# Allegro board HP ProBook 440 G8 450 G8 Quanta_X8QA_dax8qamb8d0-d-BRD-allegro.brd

Outline 218.84 x 120.25 mm; copper layers: TOP, SGND, IN1, SVCC, IN2, IN3, SGND1, BOTTOM. Coordinates in mm from the lower left corner of the outline.

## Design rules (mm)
constraint set DEFAULT: min track width 0.109
net group DFP-S3.1W10-T123B: nets N38936236 N38936237
net group W4.5-T13B: nets VCCSENSE VSSSENSE
net group W8(8: nets GPU_VCC_SENSE GPU_VSS_SENSE
net group W12-T13B: nets PCIE_RCOMPN PCIE_RCOMPP
net group W15-T123B: nets +VCCSTG CFG_RCOMP
net group DFP-S3.5(3.1: nets USB30_RX1+ USB30_RX1- USB30_RX2+ USB30_RX2- USB30_RX4+ USB30_RX4- USB30_TX1+ USB30_TX1+_C USB30_TX1- USB30_TX1-_C USB30_TX2+ USB30_TX2+_C USB30_TX2- USB30_TX2-_C USB30_TX4+ USB30_TX4-
net group DFP-S4.5(3.5: nets C_TX0_HDMI+ C_TX0_HDMI- C_TX1_HDMI+ C_TX1_HDMI- C_TX2_HDMI+ C_TX2_HDMI- C_TXC_HDMI+ C_TXC_HDMI- CCG6_SBU1_A CCG6_SBU1_A_M CCG6_SBU1_R_A CCG6_SBU2_A CCG6_SBU2_A_M CCG6_SBU2_R_A CK_XDP_N CK_XDP_P CLK_GFX_N CLK_GFX_P CLK_PCIE_CRN CLK_PCIE_CRP CLK_PCIE_LANN CLK_PCIE_LANN_R CLK_PCIE_LANP CLK_PCIE_LANP_R CLK_PCIE_SSDN CLK_PCIE_SSDP CLK_PCIE_WLANN CLK_PCIE_WLANP CLK_PCIE_WWANN CLK_PCIE_WWANP EDIDCLK_R EDIDDATA_R IN_CLK IN_CLK# IN_D0 IN_D0# IN_D1 IN_D1# IN_D2 IN_D2# INT_EDP_AUXN INT_EDP_AUXP INT_EDP_TXN0 INT_EDP_TXN1 INT_EDP_TXP0 INT_EDP_TXP1 M_A_CLKN0 M_A_CLKN1 M_A_CLKP0 M_A_CLKP1 M_B_CLKN0 M_B_CLKN1 M_B_CLKP0 M_B_CLKP1 PCIE_RXN5_LAN PCIE_RXN6_SD PCIE_RXN6_SD_C PCIE_RXN7_WLAN PCIE_RXN8_WWAN PCIE_RXN9_SSD PCIE_RXN10_SSD PCIE_RXN11_SSD PCIE_RXN12_SSD PCIE_RXP5_LAN PCIE_RXP6_SD PCIE_RXP6_SD_C PCIE_RXP7_WLAN PCIE_RXP8_WWAN PCIE_RXP9_SSD PCIE_RXP10_SSD PCIE_RXP11_SSD PCIE_RXP12_SSD PCIE_TXN5_LAN_C PCIE_TXN6_SD PCIE_TXN6_SD_C PCIE_TXN7_WLAN PCIE_TXN7_WLAN_C PCIE_TXN8_WWAN PCIE_TXN8_WWAN_C PCIE_TXN9_SSD PCIE_TXN9_SSD_C PCIE_TXN10_SSD PCIE_TXN10_SSD_C1 PCIE_TXN11_SSD PCIE_TXN11_SSD_C PCIE_TXN12_SSD PCIE_TXN12_SSD_C PCIE_TXP5_LAN_C PCIE_TXP6_SD PCIE_TXP6_SD_C PCIE_TXP7_WLAN PCIE_TXP7_WLAN_C PCIE_TXP8_WWAN PCIE_TXP8_WWAN_C PCIE_TXP9_SSD PCIE_TXP9_SSD_C PCIE_TXP10_SSD PCIE_TXP10_SSD_C1 PCIE_TXP11_SSD PCIE_TXP11_SSD_C PCIE_TXP12_SSD PCIE_TXP12_SSD_C PEX_TSTCLK PEX_TSTCLK# TBTA_SSRX1_N TBTA_SSRX1_N_C TBTA_SSRX1_P TBTA_SSRX1_P_C TBTA_SSRX2_N TBTA_SSRX2_N_C TBTA_SSRX2_P TBTA_SSRX2_P_C TBTA_SSTX1_N TBTA_SSTX1_N_C TBTA_SSTX1_P TBTA_SSTX1_P_C TBTA_SSTX2_N TBTA_SSTX2_N_C TBTA_SSTX2_P TBTA_SSTX2_P_C TCP0_AUX_DN TCP0_AUX_DN_R TCP0_AUX_DP TCP0_AUX_DP_R TCP0_DIRECT_TX0_R_DN TCP0_DIRECT_TX0_R_DP TCP0_DIRECT_TX1_R_DN TCP0_DIRECT_TX1_R_DP TCP0_DIRECT_TXRX0_R_DN TCP0_DIRECT_TXRX0_R_DP TCP0_DIRECT_TXRX1_R_DN TCP0_DIRECT_TXRX1_R_DP TCP0_TX_N0 TCP0_TX_N0_C TCP0_TX_N1 TCP0_TX_N1_C TCP0_TX_P0 TCP0_TX_P0_C TCP0_TX_P1 TCP0_TX_P1_C TCP0_TXRX_N0 TCP0_TXRX_N0_C TCP0_TXRX_N1 TCP0_TXRX_N1_C TCP0_TXRX_P0 TCP0_TXRX_P0_C TCP0_TXRX_P1 TCP0_TXRX_P1_C TCP1_AUX_DN_C TCP1_AUX_DP_C TX0_HDMI+ TX0_HDMI- TX1_HDMI+ TX1_HDMI- TX2_HDMI+ TX2_HDMI- TXC_HDMI+ TXC_HDMI- TXLOUT0+ TXLOUT0- TXLOUT1+ TXLOUT1- TYPEC3_RX1N_C TYPEC3_RX1P_C TYPEC3_RX2N_C TYPEC3_RX2P_C TYPEC3_TX1N_C TYPEC3_TX1P_C TYPEC3_TX2N_C TYPEC3_TX2P_C USB_CYPRESS_BOT_DN USB_CYPRESS_BOT_DP USB_CYPRESS_TOP_DN USB_CYPRESS_TOP_DP USBC_ALT_AUX_NBIAS USBC_ALT_AUX_PBIAS USBP1+ USBP1+_C USBP1+_CHA USBP1- USBP1-_C USBP1-_CHA USBP2+ USBP2+_C USBP2- USBP2-_C USBP4+ USBP4+_C USBP4- USBP4-_C USBP5+ USBP5- USBP6+ USBP6- USBP7+ USBP7+_C USBP7- USBP7-_C USBP8+ USBP8+_C USBP8- USBP8-_C USBP9+ USBP9- USBP10+ USBP10+_C USBP10- USBP10-_C VMA_CLK0 VMA_CLK0# VMA_CLK1 VMA_CLK1# VMA_WCK01 VMA_WCK01# VMA_WCK23 VMA_WCK23# VMA_WCK45 VMA_WCK45# VMA_WCK67 VMA_WCK67# WR_CLK_DN WR_CLK_DP WR_LANE0_DN WR_LANE0_DP WR_LANE1_DN WR_LANE1_DP WT_CLK_DN WT_CLK_DP WT_LANE0_DN WT_LANE0_DP WT_LANE1_DN WT_LANE1_DP
net group DFP-S4.5(6: nets PEG_RXN1 PEG_RXN1_C PEG_RXN2 PEG_RXN2_C PEG_RXN3 PEG_RXN3_C PEG_RXN4 PEG_RXN4_C PEG_RXP1 PEG_RXP1_C PEG_RXP2 PEG_RXP2_C PEG_RXP3 PEG_RXP3_C PEG_RXP4 PEG_RXP4_C PEG_TXN1 PEG_TXN1_C PEG_TXN2 PEG_TXN2_C PEG_TXN3 PEG_TXN3_C PEG_TXN4 PEG_TXN4_C PEG_TXP1 PEG_TXP1_C PEG_TXP2 PEG_TXP2_C PEG_TXP3 PEG_TXP3_C PEG_TXP4 PEG_TXP4_C
net group DFP-S7(4.5: nets 27M_XTAL_IN 27M_XTAL_OUT M_A_DQSN0 M_A_DQSN1 M_A_DQSN2 M_A_DQSN3 M_A_DQSN4 M_A_DQSN5 M_A_DQSN6 M_A_DQSN7 M_A_DQSP0 M_A_DQSP1 M_A_DQSP2 M_A_DQSP3 M_A_DQSP4 M_A_DQSP5 M_A_DQSP6 M_A_DQSP7 M_B_DQSN0 M_B_DQSN1 M_B_DQSN2 M_B_DQSN3 M_B_DQSN4 M_B_DQSN5 M_B_DQSN6 M_B_DQSN7 M_B_DQSP0 M_B_DQSP1 M_B_DQSP2 M_B_DQSP3 M_B_DQSP4 M_B_DQSP5 M_B_DQSP6 M_B_DQSP7
net group M_0_DQ_0: nets M_0_DQ_0<0> M_0_DQ_0<1> M_0_DQ_0<2> M_0_DQ_0<3> M_0_DQ_0<4> M_0_DQ_0<5> M_0_DQ_0<6> M_0_DQ_0<7>
net group M_0_DQ_1: nets M_0_DQ_1<0> M_0_DQ_1<1> M_0_DQ_1<2> M_0_DQ_1<3> M_0_DQ_1<4> M_0_DQ_1<5> M_0_DQ_1<6> M_0_DQ_1<7>
net group M_0_DQ_2: nets M_0_DQ_2<0> M_0_DQ_2<1> M_0_DQ_2<2> M_0_DQ_2<3> M_0_DQ_2<4> M_0_DQ_2<5> M_0_DQ_2<6> M_0_DQ_2<7>
net group M_0_DQ_3: nets M_0_DQ_3<0> M_0_DQ_3<1> M_0_DQ_3<2> M_0_DQ_3<3> M_0_DQ_3<4> M_0_DQ_3<5> M_0_DQ_3<6> M_0_DQ_3<7>
net group M_0_DQ_4: nets M_0_DQ_4<0> M_0_DQ_4<1> M_0_DQ_4<2> M_0_DQ_4<3> M_0_DQ_4<4> M_0_DQ_4<5> M_0_DQ_4<6> M_0_DQ_4<7>
net group M_0_DQ_5: nets M_0_DQ_5<0> M_0_DQ_5<1> M_0_DQ_5<2> M_0_DQ_5<3> M_0_DQ_5<4> M_0_DQ_5<5> M_0_DQ_5<6> M_0_DQ_5<7>
net group M_0_DQ_6: nets M_0_DQ_6<0> M_0_DQ_6<1> M_0_DQ_6<2> M_0_DQ_6<3> M_0_DQ_6<4> M_0_DQ_6<5> M_0_DQ_6<6> M_0_DQ_6<7>
net group M_0_DQ_7: nets M_0_DQ_7<0> M_0_DQ_7<1> M_0_DQ_7<2> M_0_DQ_7<3> M_0_DQ_7<4> M_0_DQ_7<5> M_0_DQ_7<6> M_0_DQ_7<7>
net group M_1_DQ_0: nets M_1_DQ_0<0> M_1_DQ_0<1> M_1_DQ_0<2> M_1_DQ_0<3> M_1_DQ_0<4> M_1_DQ_0<5> M_1_DQ_0<6> M_1_DQ_0<7>
net group M_1_DQ_1: nets M_1_DQ_1<0> M_1_DQ_1<1> M_1_DQ_1<2> M_1_DQ_1<3> M_1_DQ_1<4> M_1_DQ_1<5> M_1_DQ_1<6> M_1_DQ_1<7>
net group M_1_DQ_2: nets M_1_DQ_2<0> M_1_DQ_2<1> M_1_DQ_2<2> M_1_DQ_2<3> M_1_DQ_2<4> M_1_DQ_2<5> M_1_DQ_2<6> M_1_DQ_2<7>
net group M_1_DQ_3: nets M_1_DQ_3<0> M_1_DQ_3<1> M_1_DQ_3<2> M_1_DQ_3<3> M_1_DQ_3<4> M_1_DQ_3<5> M_1_DQ_3<6> M_1_DQ_3<7>
net group M_1_DQ_4: nets M_1_DQ_4<0> M_1_DQ_4<1> M_1_DQ_4<2> M_1_DQ_4<3> M_1_DQ_4<4> M_1_DQ_4<5> M_1_DQ_4<6> M_1_DQ_4<7>
net group M_1_DQ_5: nets M_1_DQ_5<0> M_1_DQ_5<1> M_1_DQ_5<2> M_1_DQ_5<3> M_1_DQ_5<4> M_1_DQ_5<5> M_1_DQ_5<6> M_1_DQ_5<7>
net group M_1_DQ_6: nets M_1_DQ_6<0> M_1_DQ_6<1> M_1_DQ_6<2> M_1_DQ_6<3> M_1_DQ_6<4> M_1_DQ_6<5> M_1_DQ_6<6> M_1_DQ_6<7>
net group M_1_DQ_7: nets M_1_DQ_7<0> M_1_DQ_7<1> M_1_DQ_7<2> M_1_DQ_7<3> M_1_DQ_7<4> M_1_DQ_7<5> M_1_DQ_7<6> M_1_DQ_7<7>
net group PCN8000: nets +3V_VCC +5VPCU +VAC +VAC_IN AMBER_BATLED# BARREL_ADP_EN BAT_GRNLED# LIMIT_SIGNAL N25318825 N25319146 N25319276 VADPBL
net group W4.3(3.1: nets ACZ_RST# ACZ_RST#_AUDIO ACZ_SDIN0_AUDIO ACZ_SDOUT ACZ_SDOUT_AUDIO ACZ_SYNC ACZ_SYNC_AUDIO BIT_CLK BIT_CLK_AUDIO BK_DIGITAL_CLK CL_CLK CL_DATA CLK_BIASREF CNV_BRI_DT CNV_BRI_RSP CNV_BRI_RSP_R CNV_RGI_DT CNV_RGI_RSP CNV_RGI_RSP_R CPU_SVID_CLK CPU_SVID_DAT CPU_VIDALERT# DDR3_DRAMRST# DPB_DDCCLK DPB_DDCDATA EC_PECI ESPI_0 ESPI_1 ESPI_2 ESPI_3 ESPI_CLK ESPI_CS# ESPI_CS#_L_R ESPI_EC_IO0_R_R ESPI_EC_IO1_R_R ESPI_EC_IO2_R_R ESPI_EC_IO3_R_R FT_DIGITAL_CLK FT_DIGITAL_CLK_L FT_DIGITAL_D1_L GPUT_CLK_L GPUT_DATA_L HD_SDIN0 HDMI_UP_CLK HDMI_UP_DATA I2CA_SCL IM_5S_CLK IM_5S_DAT LPC_ESPI_CLK_R_R PCH_DPST_PWM PCH_KBC_CLK PCH_KBC_DATA PCH_SMB_CLK PCH_SMB_DATA PCH_SMBCLK PCH_SMBDATA PCI_PLTRST# PCIE_CLKREQ_CR# PCIE_CLKREQ_LAN# PCIE_CLKREQ_SSD# PCIE_CLKREQ_WLAN# PCIE_CLKREQ_WWAN# PCIE_REQ_GPU# PD_I2C_SCL3 PD_I2C_SDA3 PM_THRMTRIP# PROCHOT#_CPU RTC_X1 RTC_X1_R RTC_X2 RTC_X2_R SCL_BAT_CHG SD_CD#_R SD_CMD_R SD_MMC_CD# SD_MMC_CLK SD_MMC_CLK_C SD_MMC_CMD SD_MMC_DATA0 SD_MMC_DATA0_C SD_MMC_DATA1 SD_MMC_DATA1_C SD_MMC_DATA2 SD_MMC_DATA2_C SD_MMC_DATA3 SD_MMC_DATA3_C SD_MMC_WP SDA_BAT_CHG SMB_PCH_CLK SMB_PCH_DAT SUSCLK32_KBC THERM_SCL THERM_SDA TPCLK-1 TPDATA-1 UIM_CLK UIM_DATA VADJ1 VR_SVID_ALERT# VR_SVID_CLK VR_SVID_DATA XTAL_38P4M_IN XTAL_38P4M_IN_R XTAL_38P4M_OUT XTAL_38P4M_OUT_R
net group W4.3(3.1: nets BIOS_WP# CPU_PROCHOT# FAN1_PWM H_VCCST_PWRGD PCH_SPI1_CLK PCH_SPI1_CLK_E1 PCH_SPI1_CLK_E2 PCH_SPI1_CLK_R1 PCH_SPI1_CLK_R2 PCH_SPI1_SI PCH_SPI1_SI_E1 PCH_SPI1_SI_E2 PCH_SPI1_SI_R1 PCH_SPI1_SI_R2 PCH_SPI1_SO PCH_SPI1_SO_E1 PCH_SPI1_SO_E2 PCH_SPI1_SO_R1 PCH_SPI1_SO_R2 PCH_SPI_CS0# PCH_SPI_CS0#_E1 PCH_SPI_CS0#_E2 PCH_SPI_CS0#_R1 PCH_SPI_CS0#_R2 PCH_SPI_IO2 PCH_SPI_IO2_R1 PCH_SPI_IO2_R2 PCH_SPI_IO3 PCH_SPI_IO3_R1 PCH_SPI_IO3_R2 PVT_CS# PVT_CS#_L PVT_DIO2 PVT_DIO2_L PVT_DIO3 PVT_DIO3_L PVT_HOLD PVT_MOSI PVT_MOSI_L PVT_SCLK PVT_SCLK_L PVT_SPI_MISO PVT_SPI_MISO_L PVT_SPI_MISO_R RSMRST# RTC_RST# SRTC_RST#
net group W5.5(4: nets FBA_CMD0 FBA_CMD1 FBA_CMD2 FBA_CMD3 FBA_CMD4 FBA_CMD5 FBA_CMD6 FBA_CMD7 FBA_CMD8 FBA_CMD9 FBA_CMD10 FBA_CMD11 FBA_CMD12 FBA_CMD13 FBA_CMD14 FBA_CMD15 FBA_CMD16 FBA_CMD17 FBA_CMD18 FBA_CMD19 FBA_CMD20 FBA_CMD21 FBA_CMD22 FBA_CMD23 FBA_CMD24 FBA_CMD25 FBA_CMD26 FBA_CMD27 FBA_CMD28 FBA_CMD29 FBA_CMD30 FBA_CMD31 FBA_DBI0 FBA_DBI1 FBA_DBI2 FBA_DBI3 FBA_DBI4 FBA_DBI5 FBA_DBI6 FBA_DBI7 FBA_EDC0 FBA_EDC1 FBA_EDC2 FBA_EDC3 FBA_EDC4 FBA_EDC5 FBA_EDC6 FBA_EDC7 M_A_A0 M_A_A1 M_A_A2 M_A_A3 M_A_A4 M_A_A5 M_A_A6 M_A_A7 M_A_A8 M_A_A9 M_A_A10 M_A_A11 M_A_A12 M_A_A13 M_A_ACT# M_A_ALERT# M_A_BG#0 M_A_BG#1 M_A_BS#0 M_A_BS#1 M_A_CAS# M_A_CKE0 M_A_CKE1 M_A_CS#0 M_A_CS#1 M_A_ODT0 M_A_ODT1 M_A_PARITY M_A_RAS# M_A_WE# M_B_A0 M_B_A1 M_B_A2 M_B_A3 M_B_A4 M_B_A5 M_B_A6 M_B_A7 M_B_A8 M_B_A9 M_B_A10 M_B_A11 M_B_A12 M_B_A13 M_B_ACT# M_B_ALERT# M_B_BG#0 M_B_BG#1 M_B_BS#0 M_B_BS#1 M_B_CAS# M_B_CKE0 M_B_CKE1 M_B_CS#0 M_B_CS#1 M_B_ODT0 M_B_ODT1 M_B_PARITY M_B_RAS# M_B_WE# VMA_DQ0 VMA_DQ1 VMA_DQ2 VMA_DQ3 VMA_DQ4 VMA_DQ5 VMA_DQ6 VMA_DQ7 VMA_DQ8 VMA_DQ9 VMA_DQ10 VMA_DQ11 VMA_DQ12 VMA_DQ13 VMA_DQ14 VMA_DQ15 VMA_DQ16 VMA_DQ17 VMA_DQ18 VMA_DQ19 VMA_DQ20 VMA_DQ21 VMA_DQ22 VMA_DQ23 VMA_DQ24 VMA_DQ25 VMA_DQ26 VMA_DQ27 VMA_DQ28 VMA_DQ29 VMA_DQ30 VMA_DQ31 VMA_DQ32 VMA_DQ33 VMA_DQ34 VMA_DQ35 VMA_DQ36 VMA_DQ37 VMA_DQ38 VMA_DQ39 VMA_DQ40 VMA_DQ41 VMA_DQ42 VMA_DQ43 VMA_DQ44 VMA_DQ45 VMA_DQ46 VMA_DQ47 VMA_DQ48 VMA_DQ49 VMA_DQ50 VMA_DQ51 VMA_DQ52 VMA_DQ53 VMA_DQ54 VMA_DQ55 VMA_DQ56 VMA_DQ57 VMA_DQ58 VMA_DQ59 VMA_DQ60 VMA_DQ61 VMA_DQ62 VMA_DQ63
net group W8-T123B: nets DDR_VTT
net group W10-T123B: nets +5V_HDMIC +SMDDR_VREF_DQ0 +SMDDR_VREF_DQ1 +VCCST DDR_VTTREF HPOUT_L HPOUT_L_C HPOUT_L_L HPOUT_R HPOUT_R_C HPOUT_R_R SLEEVE_C SLEEVE_L TYPEC_CC1 TYPEC_CC2 TYPEC_VBUS
net group W12-T123B: nets DDR_RCOMP0
net group W20-T1B: nets DP_RCOMP
net group W20-T123B: nets +3V_RTC +3V_WLAN_P +3VLCD_CON +SMDDR_VREF_DIMM SM_VREF SMDDR_VREF_DQ1_M1 SMDDR_VREF_DQ1_M3
net group W30-T13B: nets L_SPK+ L_SPK- R_SPK+ R_SPK-
net group W40-T123B: nets MIC2-VREFO

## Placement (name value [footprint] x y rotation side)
C500  *0.1u/10V_2  [C0201]  154.38 54.31 270 top
C700  10U/6.3V_4  [C0402_2]  128.03 80.24 180 top
C701  22U/6.3V_6  [C0603]  120.16 74.28 270 top
C702  10U/6.3V_4  [C0402_2]  103.47 103.92 270 bottom
C703  10U/6.3V_4  [C0402_2]  123.42 79.82 90 top
C704  10U/6.3V_4  [C0402_2]  97.46 103.89 270 bottom
C705  10U/6.3V_4  [C0402_2]  96.84 103.42 270 top
C706  10U/6.3V_4  [C0402_2]  99.1 94.94 90 bottom
C707  1U/6.3V_4  [C0402]  127.75 70.73 270 top
C708  10U/6.3V_4  [C0402_2]  128.02 79.02 180 top
C709  22U/6.3V_6  [C0603]  122.29 75.36 180 top
C710  10U/6.3V_4  [C0402_2]  94.03 81.4 0 top
C711  10U/6.3V_4  [C0402_2]  93.29 96.59 0 bottom
C712  1U/6.3V_4  [C0402]  112.6 70.69 270 top
C713  1U/6.3V_4  [C0402]  110.5 79.12 270 top
C714  10U/6.3V_4  [C0402_2]  125.67 79.81 90 top
C715  22U/6.3V_6  [C0603]  117.33 77.62 270 top
C716  1U/6.3V_4  [C0402]  130.7 70.73 270 top
C717  *1U/6.3V_4  [C0402]  111.47 79.1 90 top
C718  *22U/6.3V_6  [C0603]  118.85 77.6 270 top
C719  1U/6.3V_4  [C0402]  129.67 70.73 270 top
C720  10U/6.3V_4  [C0402_2]  122.63 70.74 270 top
C721  *22U/6.3V_6  [C0603]  118.67 74.29 270 top
C722  1U/6.3V_4  [C0402]  128.71 70.73 270 top
C723  10U/6.3V_4  [C0402_2]  123.9 70.74 270 top
C724  *22U/6.3V_6  [C0603]  122.28 76.81 180 top
C725  10U/6.3V_4  [C0402_2]  119.04 70.45 0 top
C726  *22U/6.3V_6  [C0603]  115.55 99.74 180 top
C727  10U/6.3V_4  [C0402_2]  97.92 94.94 90 bottom
C728  1U/6.3V_4  [C0402]  131.71 70.73 270 top
C729  10U/6.3V_4  [C0402_2]  119.63 68.63 180 top
C730  *22U/6.3V_6  [C0603]  122.29 73.91 180 top
C731  10U/6.3V_4  [C0402_2]  96.72 94.94 90 bottom
C732  1U/6.3V_4  [C0402]  132.73 70.73 270 top
C733  1U/6.3V_4  [C0402]  127.33 90.62 90 bottom
C734  *1U/6.3V_4  [C0402]  126.31 90.62 270 bottom
C735  10U/6.3V_4  [C0402_2]  122.93 68.73 180 top
C736  *22U/6.3V_6  [C0603]  123.12 72.47 180 top
C737  1U/6.3V_4  [C0402]  107.01 59.54 90 top
C738  10U/6.3V_4  [C0402_2]  119.05 71.69 0 top
C739  1U/6.3V_4  [C0402]  111.53 59.99 90 top
C740  10U/6.3V_4  [C0402_2]  120.86 70.45 180 top
C741  1U/6.3V_4  [C0402]  113.87 59.84 90 top
C742  10U/6.3V_4  [C0402_2]  114.73 77.12 270 top
C743  1U/6.3V_4  [C0402]  118.26 60.02 90 top
C744  1U/6.3V_4  [C0402]  113.62 77.13 270 top
C745  10U/6.3V_4  [C0402_2]  109.43 77.13 270 top
C746  1U/6.3V_4  [C0402]  120.88 59.99 90 top
C747  1U/6.3V_4  [C0402]  112.61 77.13 270 top
C748  10U/6.3V_4  [C0402_2]  115.99 77.85 270 top
C749  1U/6.3V_4  [C0402]  124.74 57.73 315 top
C750  1U/6.3V_4  [C0402]  111.59 77.13 270 top
C751  10U/6.3V_4  [C0402_2]  115.48 101.1 180 top
C752  1U/6.3V_4  [C0402]  116.66 70.69 270 top
C753  1U/6.3V_4  [C0402]  110.57 77.13 270 top
C754  10U/6.3V_4  [C0402_2]  115.48 102.39 180 top
C755  1U/6.3V_4  [C0402]  117.68 70.69 270 top
C756  1U/6.3V_4  [C0402]  107.06 77.47 270 top
C757  10U/6.3V_4  [C0402_2]  107.05 73.57 90 top
C758  1U/6.3V_4  [C0402]  111.58 70.69 270 top
C759  1U/6.3V_4  [C0402]  110.08 72.92 90 top
C760  1U/6.3V_4  [C0402]  113.61 70.69 270 top
C761  1U/6.3V_4  [C0402]  109.12 72.41 90 top
C762  1U/6.3V_4  [C0402]  115.64 70.69 270 top
C763  1U/6.3V_4  [C0402]  124.52 79.82 90 top
C764  1U/6.3V_4  [C0402]  114.63 70.69 270 top
C765  1U/6.3V_4  [C0402]  105.37 78.68 270 top
C766  1U/6.3V_4  [C0402]  110.56 70.69 270 top
C767  1U/6.3V_4  [C0402]  107.09 75.33 90 top
C768  1U/6.3V_4  [C0402]  109.55 70.69 270 top
C769  1U/6.3V_4  [C0402]  124.69 68.66 0 top
C770  1U/6.3V_4  [C0402]  120.87 71.69 180 top
C773  22U/6.3V_6  [C0603]  125.12 90.37 270 bottom
C800  *0.1u/10V_2  [C0201]  154.91 53.16 270 top
C1100  *15P/50V_4  [C0402]  162.35 73.18 270 top
C1101  *10P/50V_2  [C0201]  148.18 59.21 90 bottom
C1300  0.22U/10V_4  [C0402]  132.48 89.84 270 top
C1301  0.22U/10V_4  [C0402]  131.49 89.84 270 top
C1302  0.1U/16V_2  [C0201]  169.06 75.84 90 bottom
C1303  0.1U/16V_2  [C0201]  169.77 75.84 90 bottom
C1304  0.1U/16V_4  [C0402]  134.49 89.41 270 top
C1305  0.1U/16V_4  [C0402]  133.47 89.41 270 top
C1306  0.22u/25V_2  [C0201]  104.42 89.51 90 bottom
C1307  0.22u/25V_2  [C0201]  105.13 89.51 90 bottom
C1308  0.22u/25V_2  [C0201]  107.26 89.51 270 bottom
C1309  0.22u/25V_2  [C0201]  107.97 89.51 270 bottom
C1310  0.22u/25V_2  [C0201]  105.84 89.51 90 bottom
C1311  0.22u/25V_2  [C0201]  108.68 89.51 270 bottom
C1312  0.22u/25V_2  [C0201]  106.55 89.51 90 bottom
C1313  0.22u/25V_2  [C0201]  109.4 89.51 270 bottom
C1400  1U/6.3V_4  [C0402]  156.4 68.57 180 top
C1401  1u/10V_2  [C0201]  158.16 66.42 180 top
C1402  1u/10V_2  [C0201]  155.73 65.97 90 top
C1403  15p/50V_4  [C0402]  148.51 53.62 90 top
C1404  10p/50V_4  [C0402]  141.25 92.99 90 bottom
C1405  15p/50V_4  [C0402]  151.61 53.21 0 top
C1406  10p/50V_4  [C0402]  143 92.99 90 bottom
C1500  *0.1U/10V_2  [C0201]  157.81 67.74 270 top
C1501  0.1U/16V/X7R_4  [C0402]  156.64 47.37 180 top
C1502  *0.01U/50V_4  [C0402]  164.05 70.3 0 top
C1503  *10P/50V_2  [C0201]  126.76 81.52 180 top
C1504  22P/50V_4  [C0402]  185.85 38.22 0 top
C1600  47U/6.3V_6  [C0603]  132.46 98.02 180 bottom
C1601  22U/6.3V_6  [C0603]  129.33 75.47 270 top
C1602  47U/6.3V_6  [C0603]  122.13 96.19 90 top
C1603  22U/6.3V_6  [C0603]  131.39 75.31 0 top
C1604  10U/10V_4  [C0402_2]  131.99 72.72 90 top
C1605  47U/6.3V_6  [C0603]  126.34 96.19 90 top
C1606  22U/6.3V_6  [C0603]  120.29 102.29 270 top
C1607  10U/10V_4  [C0402_2]  129.87 80.1 0 top
C1608  10U/10V_4  [C0402_2]  125.42 72.91 0 top
C1609  *1U/6.3V_4  [C0402]  139.16 77.14 0 top
C1610  *1U/6.3V_4  [C0402]  136 76.67 270 top
C1611  22U/6.3V_6  [C0603]  118.87 102.28 270 top
C1612  10U/10V_4  [C0402_2]  129.87 78.91 0 top
C1613  10U/10V_4  [C0402_2]  125.42 70.42 0 top
C1614  47U/6.3V_6  [C0603]  120.65 97.05 90 top
C1615  22U/6.3V_6  [C0603]  124.15 101.02 270 bottom
C1616  10U/10V_4  [C0402_2]  117.78 79.8 90 top
C1617  10U/10V_4  [C0402_2]  133.23 80.11 180 top
C1618  10U/10V_4  [C0402_2]  118.97 79.8 90 top
C1619  10U/10V_4  [C0402_2]  133.24 78.91 180 top
C1620  22U/6.3V_6  [C0603]  125.07 76.32 0 top
C1621  10U/10V_4  [C0402_2]  133.99 76.4 180 top
C1622  10U/10V_4  [C0402_2]  131.72 96.42 90 bottom
C1623  22U/6.3V_6  [C0603]  122.74 101.01 270 bottom
C1624  10U/10V_4  [C0402_2]  116.58 79.8 90 top
C1625  10U/10V_4  [C0402_2]  125.42 71.69 0 top
C1626  22U/6.3V_6  [C0603]  125.58 101.04 270 bottom
C1627  10U/10V_4  [C0402_2]  133.99 77.6 180 top
C1628  10U/10V_4  [C0402_2]  128.14 97.99 180 top
C1629  22U/6.3V_6  [C0603]  121.77 102.29 270 top
C1630  10U/10V_4  [C0402_2]  134.45 72.71 90 top
C1631  10U/10V_4  [C0402_2]  129.24 72.73 90 top
C1632  22U/6.3V_6  [C0603]  131.42 76.78 0 top
C1633  10U/10V_4  [C0402_2]  130.47 72.73 90 top
C1634  10U/10V_4  [C0402_2]  127.66 96.52 90 top
C1635  22U/6.3V_6  [C0603]  125.07 74.88 0 top
C1636  10U/10V_4  [C0402_2]  128.02 72.74 90 top
C1637  10U/10V_4  [C0402_2]  134.72 80.23 90 top
C1638  *1U/6.3V_4  [C0402]  136.95 73.05 180 top
C1639  22U/6.3V_6  [C0603]  127.91 75.47 270 top
C1640  10U/10V_4  [C0402_2]  134 74.89 180 top
C1641  *0.1U/16V_4  [C0402]  137.26 74.62 180 top
C1642  10U/10V_4  [C0402_2]  110.64 80.58 0 top
C1643  10U/10V_4  [C0402_2]  118.74 100.33 0 top
C1644  2.2U/6.3V_4  [C0402]  148.46 65.2 0 bottom
C1645  10U/10V_4  [C0402_2]  133.22 72.72 90 top
C1646  47U/6.3V_6  [C0603]  153.97 80.85 180 bottom
C1647  4.7U/6.3V_4  [C0402_2]  148.33 73.23 270 bottom
C1648  1U/6.3V_4  [C0402]  138.45 68.76 270 top
C1649  1u/10V_2  [C0201]  160.3 66.39 90 top
C1650  0.1U/16V_2  [C0201]  159.59 66.39 90 top
C1651  *1U/6.3V_4  [C0402]  138.45 70.48 270 top
C1652  *1U/6.3V_4  [C0402]  156.59 65.22 0 bottom
C1653  0.1U/16V_2  [C0201]  148.74 71.04 0 bottom
C1654  1U/6.3V_4  [C0402]  156.79 70.3 270 bottom
C1655  1U/6.3V_4  [C0402]  152.42 69.29 0 bottom
C1656  0.1U/16V_2  [C0201]  136.65 72.06 270 top
C1700  47U/6.3V_6  [C0603]  53.11 24.08 0 top
C1701  1U/6.3V_4  [C0402]  80.36 24.61 180 top
C1702  47U/6.3V_6  [C0603]  75.44 25.14 90 top
C1703  1U/6.3V_4  [C0402]  80.13 25.98 90 top
C1704  1U/6.3V_4  [C0402]  109.6 56.89 0 top
C1705  1U/6.3V_4  [C0402]  145.79 24.99 90 top
C1706  1U/6.3V_4  [C0402]  157.81 25.45 90 top
C1707  10U/6.3V_4  [C0402_2]  60.53 25.52 270 top
C1708  1U/6.3V_4  [C0402]  145.79 31.09 0 top
C1709  10U/6.3V_4  [C0402_2]  96.75 26.69 0 top
C1710  1U/6.3V_4  [C0402]  150.72 29.11 0 top
C1711  10U/6.3V_4  [C0402_2]  99.59 23.8 90 top
C1712  1U/6.3V_4  [C0402]  155.75 24.08 180 top
C1713  10U/6.3V_4  [C0402_2]  107.26 55.09 90 top
C1714  1U/6.3V_4  [C0402]  144.5 29.92 0 top
C1715  10U/6.3V_4  [C0402_2]  112.65 56.56 90 top
C1716  1U/6.3V_4  [C0402]  129.31 58.21 180 top
C1717  10U/6.3V_4  [C0402_2]  91.87 26.69 180 top
C1718  1U/6.3V_4  [C0402]  86.76 27.61 0 top
C1719  10U/6.3V_4  [C0402_2]  132.99 57.63 270 top
C1720  *1U/6.3V_2  [C0201]  116.69 26.74 0 top
C1721  10U/6.3V_4  [C0402_2]  130.91 57.12 180 top
C1722  *1U/6.3V_2  [C0201]  87.63 24.56 0 top
C1723  10U/6.3V_4  [C0402_2]  102.64 22.4 90 top
C1724  1U/6.3V_4  [C0402]  80.59 22.91 270 top
C1725  10U/6.3V_4  [C0402_2]  134.82 55.55 0 top
C1726  *1U/6.3V_2  [C0201]  124.15 26.44 180 top
C1727  1U/6.3V_4  [C0402]  70.1 26.06 90 top
C1800  0.1U/16V_2  [C0201]  201.78 40.05 90 bottom
C1801  0.1U/16V_2  [C0201]  23.73 28.34 90 top
C1802  0.1U/16V_2  [C0201]  192.78 2.61 180 top
C1803  0.1U/16V_2  [C0201]  25.93 34.03 270 top
C1804  0.1U/16V_2  [C0201]  200.35 41.53 180 bottom
C1805  0.1U/16V_2  [C0201]  196.92 2.99 270 top
C1806  0.1U/16V_2  [C0201]  26.9 36.83 270 top
C1807  0.1U/25V_4  [C0402]  25.17 29.33 180 top
C1808  0.1U/16V_2  [C0201]  203.12 26.85 180 bottom
C1809  0.1U/16V_2  [C0201]  142.72 15.77 90 top
C1810  0.1U/16V_2  [C0201]  170.67 8.66 270 top
C1811  0.1U/16V_2  [C0201]  201.12 28.42 270 bottom
C1812  0.1U/16V_2  [C0201]  142.23 16.67 0 top
C1813  0.1U/16V_2  [C0201]  176.38 7.44 0 bottom
C1815  0.1U/16V_2  [C0201]  13.94 18.68 180 top
C1816  0.1U/16V_2  [C0201]  180.82 26.93 180 top
C1818  0.1U/16V_2  [C0201]  14.04 15.08 180 top
C1819  0.1U/16V_2  [C0201]  184.44 28.36 180 top
C1900  0.1U/16V_2  [C0201]  45.79 14.37 180 top
C1902  0.1U/16V_2  [C0201]  146 8.86 0 top
C1903  0.1U/16V_2  [C0201]  41.6 12.9 180 top
C1905  0.1U/16V_2  [C0201]  148.07 11.22 270 top
C1906  0.1U/16V_2  [C0201]  111.25 15.19 90 top
C1907  0.1U/16V_2  [C0201]  167.28 98.32 180 top
C1908  0.1U/16V_2  [C0201]  193.5 55.83 90 top
C1909  0.1U/16V_2  [C0201]  109.55 16.91 0 top
C1910  0.1U/16V_2  [C0201]  169.37 96.04 180 top
C1911  0.1U/16V_2  [C0201]  190.96 57.6 0 top
C1912  0.1U/16V_2  [C0201]  162.81 9.8 0 top
C1913  0.1U/16V_2  [C0201]  160.55 9.47 0 top
C1914  0.1U/16V_2  [C0201]  168.87 69.21 0 top
C1915  *0.1U/16V_2  [C0201]  27.96 52.88 0 top
C1916  0.1U/16V_2  [C0201]  25.6 65.63 0 top
C1917  *0.1U/16V_2  [C0201]  30.38 54.45 270 top
C1918  0.1U/16V_2  [C0201]  170.74 72.21 270 top
C1919  0.1U/16V_2  [C0201]  27.68 67 180 top
C2000  0.1U/16V_2  [C0201]  74.65 12.16 180 top
C2001  *0.1U/16V_2  [C0201]  120.22 90.5 0 top
C2002  0.1U/16V_2  [C0201]  19.06 12.89 180 top
C2004  0.1U/16V_2  [C0201]  17.22 9.78 180 top
C2005  0.1U/25V_4  [C0402]  72.41 10.69 270 top
C2006  *0.1U/16V_2  [C0201]  122.91 93.36 270 top
C2008  0.1U/16V_2  [C0201]  200.48 75.64 180 top
C2009  0.1U/16V_2  [C0201]  175.49 51.81 0 top
C2010  0.1U/16V_2  [C0201]  176.22 103.45 270 bottom
C2011  0.1U/16V_2  [C0201]  142.97 6.02 180 top
C2012  0.1U/16V_2  [C0201]  198.7 77.29 90 top
C2013  0.1U/16V_2  [C0201]  181.22 49.64 180 top
C2014  0.1U/16V_2  [C0201]  177.41 103.51 0 bottom
C2015  0.1U/16V_2  [C0201]  152.29 7.44 270 top
C2016  0.1U/16V_2  [C0201]  21.52 25.36 0 top
C2018  0.1U/16V_2  [C0201]  82.52 110.56 90 top
C2019  0.1U/16V_2  [C0201]  20.01 27.08 90 top
C2021  0.1U/25V_4  [C0402]  86.23 111.15 90 top
C2800  *0.1U/16V_4  [C0402]  142.97 23.11 270 top
C2801  1U/6.3V_4  [C0402]  177.8 25.75 270 top
C2802  1U/6.3V_4  [C0402]  144.93 22.15 270 top
C2803  1U/6.3V_4  [C0402]  148.71 24.66 90 top
C2804  1U/6.3V_4  [C0402]  141.5 22.15 90 top
C2805  1U/6.3V_4  [C0402]  165.73 25.98 270 top
C2806  1U/6.3V_4  [C0402]  159.51 25.85 180 top
C2807  *1U/6.3V_2  [C0201]  126.13 24.86 90 top
C2808  *1U/6.3V_2  [C0201]  119.35 21.92 270 top
C2809  10U/6.3V_4  [C0402_2]  150.8 22.12 270 top
C2810  10U/6.3V_4  [C0402_2]  151.94 26.13 90 top
C2811  10U/6.3V_4  [C0402_2]  146.43 22.1 270 top
C2812  *1U/6.3V_2  [C0201]  130.4 21.97 90 top
C2813  10U/6.3V_4  [C0402_2]  137.49 24.15 0 top
C2814  10U/6.3V_4  [C0402_2]  173.86 21.89 270 top
C2815  10U/6.3V_4  [C0402_2]  163.45 21.84 270 top
C2816  10U/6.3V_4  [C0402_2]  150.09 23.7 180 top
C2817  1U/6.3V_4  [C0402]  102.75 10.92 180 bottom
C2818  1U/6.3V_4  [C0402]  184.12 22.23 180 top
C2819  1U/6.3V_4  [C0402]  184.12 19.22 180 top
C2821  10U/6.3V_4  [C0402_2]  183.62 17.88 90 top
C2822  *0.1U/16V_4  [C0402]  155.83 20.22 90 top
C2823  *2.2U/10V_4  [C0402]  156.79 20.22 90 top
C2824  0.1U/16V_4  [C0402]  180.84 25.56 0 top
C2825  2.2U/10V_4  [C0402]  180.85 24.56 0 top
C2826  0.1U/16V_4  [C0402]  163.88 38.71 90 top
C2827  2.2U/10V_4  [C0402]  164.9 38.71 90 top
C2828  0.022U/25V_4  [C0402]  154.02 23.21 270 top
C2900  *0.1U/16V_4  [C0402]  65.07 21.89 270 top
C2901  1U/6.3V_4  [C0402]  57.78 24.86 270 top
C2903  1U/6.3V_4  [C0402]  53.41 21.84 270 top
C2904  1U/6.3V_4  [C0402]  182.55 17.88 90 top
C2905  1U/6.3V_4  [C0402]  42.42 21.84 90 top
C2907  1U/6.3V_4  [C0402]  90.68 24.86 270 top
C2908  1U/6.3V_4  [C0402]  106.8 21.99 90 top
C2909  1U/6.3V_4  [C0402]  87.09 21.92 270 top
C2910  10U/6.3V_4  [C0402_2]  104.82 24.31 0 top
C2911  1U/6.3V_4  [C0402]  77.95 23.95 0 top
C2912  1U/6.3V_4  [C0402]  96.9 21.87 270 top
C2913  0.1U/16V_4  [C0402]  104.42 26.21 90 top
C2914  1U/6.3V_4  [C0402]  73.91 27.3 0 top
C2915  2.2U/10V_4  [C0402]  106.5 26.11 180 top
C2916  10U/6.3V_4  [C0402_2]  72.64 25.17 180 top
C2917  10U/6.3V_4  [C0402_2]  69.14 22.63 270 top
C2918  10U/6.3V_4  [C0402_2]  70.97 22.27 270 top
C2919  10U/6.3V_4  [C0402_2]  78.74 21.79 180 top
C2920  *0.1U/25V_2  [C0201]  109.29 26.21 270 top
C2921  10U/6.3V_4  [C0402_2]  72.44 21.92 270 top
C2922  *2.2U/10V_2  [C0201]  180.92 23.7 180 top
C2923  10U/6.3V_4  [C0402_2]  83.51 27.28 90 top
C2924  10U/6.3V_4  [C0402_2]  75.39 21.71 270 top
C2925  10U/6.3V_4  [C0402_2]  67.99 26.41 90 top
C2926  *0.1U/25V_2  [C0201]  110.95 22.43 180 top
C2927  *2.2U/10V_2  [C0201]  110.95 23.31 180 top
C2928  0.022U/6.3V_2  [C0201]  113.49 20.88 0 top
C2929  *0.022U/25V_4  [C0402]  114.3 21.71 180 top
C3300  *0.1U/16V_4  [C0402]  23.98 45.54 0 top
C3400  0.1U/16V_4  [C0402]  30.83 45.85 180 top
C3401  *100p/50V_4  [C0402]  22.12 51.63 0 top
C3403  82P/50V_4  [C0402]  31.6 40.04 180 bottom
C3404  0.01U/50V_4  [C0402]  31.6 43.14 180 bottom
C3405  0.1U/16V_4  [C0402]  31.59 42.18 180 bottom
C3406  10U/6.3V_4  [C0402_2]  31.6 41.11 180 bottom
C3407  2200P/50V_4  [C0402]  30.37 39.05 180 bottom
C3408  0.047U/25V_4  [C0402]  31.6 44.1 0 bottom
C3409  0.1U/25V_2  [C0201]  32.52 30.75 90 top
C3410  10P/50V_4  [C0402]  28.7 28.01 90 top
C3411  0.1U/25V_2  [C0201]  33.53 30.75 90 top
C3412  0.01U/50V_4  [C0402]  26.08 32 0 top
C3413  0.1U/25V_4  [C0402]  26.08 33.02 180 top
C3414  1000P/50V_4  [C0402]  27.2 27.76 270 top
C3415  0.1U/16V_4  [C0402]  32.59 25.98 180 top
C3416  10P/50V_4  [C0402]  30.75 26.69 270 top
C3417  0.1U/16V_4  [C0402]  32.59 26.95 180 top
C3418  0.1U/16V_4  [C0402]  32.72 33.53 180 top
C3419  0.1U/16V_4  [C0402]  32.72 34.55 180 top
C3420  *1uF/6.3_2  [C0201]  28.75 56.03 0 bottom
C3421  *0.1U/10V_2  [C0201]  29.51 50.11 180 bottom
C3422  *1U/6.3V_4  [C0402]  27.76 49.98 0 bottom
C3423  *22U/6.3V_6  [C0603]  26.62 44.77 0 top
C3425  0.01U/50V_4  [C0402]  24.88 42.67 90 top
C3426  4.7U/6.3V_4  [C0402_2]  25.97 42.67 90 top
C3427  22p/50V_4  [C0402]  27.92 39.73 90 top
C3500  0.1U/16V_4  [C0402]  202.89 46.2 90 top
C3501  *10U/6.3V_4  [C0402_2]  204.04 46.05 90 top
C3502  *0.01U/50V_4  [C0402]  205.13 46.05 90 top
C3503  0.1U/16V_4  [C0402]  194.99 49.58 270 top
C3504  *220P/50V_4  [C0402]  204.72 44.32 180 top
C3505  0.1U/16V_4  [C0402]  195.35 58.06 0 top
C3506  0.1U/16V_4  [C0402]  195.35 57.05 0 top
C3507  0.1U/16V_4  [C0402]  195.37 56.06 0 top
C3508  0.1U/16V_4  [C0402]  195.37 55.04 0 top
C3521  0.1U/16V_4  [C0402]  195.37 54.05 0 top
C3522  0.1U/16V_4  [C0402]  195.37 53.03 0 top
C3523  0.1U/16V_4  [C0402]  195.37 52.02 0 top
C3524  0.1U/16V_4  [C0402]  195.37 51 0 top
C3525  0.1U/16V_4  [C0402]  202.66 52.68 90 top
C3526  *10P/50V_4  [C0402]  203.96 50.66 0 top
C3527  *10P/50V_4  [C0402]  203.15 48.59 0 top
C3528  0.1U/16V_4  [C0402]  202.56 63.02 270 top
C3529  0.1U/16V_4  [C0402]  201.55 63.02 270 top
C3530  0.1U/16V_4  [C0402]  197.54 51.46 90 top
C3531  0.1U/16V_4  [C0402]  198.5 51.46 90 top
C3600  1u/25V_6  [C0603]  201.14 39.98 0 top
C3601  1u/25V_6  [C0603]  200.3 41.4 180 top
C3602  10U/6.3V_4  [C0402_2]  198.22 39.29 270 bottom
C3603  2.2U/10V_4  [C0402]  200 35.82 180 top
C3604  10U/6.3V_4  [C0402_2]  200.56 34.29 270 top
C3605  10U/6.3V_4  [C0402_2]  198.32 41.68 90 top
C3606  0.1U/16V_4  [C0402]  199.03 34.74 180 top
C3607  10U/6.3V_4  [C0402_2]  199.03 33.67 0 top
C3608  10U/6.3V_4  [C0402_2]  197.14 42.36 270 top
C3609  10U/6.3V_4  [C0402_2]  189.61 46.3 180 top
C3610  0.1U/16V_4  [C0402]  189.61 45.2 0 top
C3611  10U/6.3V_4  [C0402_2]  194.43 40.46 270 bottom
C3612  0.1U/16V_4  [C0402]  195.53 40.46 90 bottom
C3613  10U/6.3V_4  [C0402_2]  196.72 33.47 0 top
C3614  10U/6.3V_4  [C0402_2]  192.25 40.46 270 bottom
C3615  0.1U/16V_4  [C0402]  193.34 40.46 90 bottom
C3616  0.1U/16V_4  [C0402]  191.95 34.62 180 top
C3617  *100p/50V_4  [C0402]  190.57 34.36 270 top
C3618  10U/6.3V_4  [C0402_2]  189.48 41.32 90 top
C3619  0.1U/16V_4  [C0402]  190.55 41.31 270 top
C3620  10U/6.3V_4  [C0402_2]  192.63 37.23 0 bottom
C3621  0.1U/16V_4  [C0402]  192.63 38.38 180 bottom
C3622  10U/6.3V_4  [C0402_2]  190.17 37.72 180 top
C3623  *22P/50V_4  [C0402]  190.17 38.81 180 top
C3624  0.1U/16V_4  [C0402]  189.33 43.23 270 top
C3625  1000P/50V_4  [C0402]  136.17 100.95 0 top
C3626  1000P/50V_4  [C0402]  137.89 100.95 180 top
C3627  1000P/50V_4  [C0402]  140.03 100.93 0 top
C3628  1000P/50V_4  [C0402]  142.2 100.95 0 top
C3700  100P/50V_4  [C0402]  202.68 36.83 180 top
C3701  100P/50V_4  [C0402]  200.05 34.72 0 bottom
C3702  100P/50V_4  [C0402]  202.46 34.69 270 top
C4100  0.1U/16V_4  [C0402]  192.64 72.91 90 top
C4101  0.1U/16V_4  [C0402]  191.66 72.91 90 top
C4103  10U/6.3V_4  [C0402_2]  190.58 72.75 270 top
C4105  *1u/6.3V_4  [C0402]  194.26 73.2 90 top
C4109  *0.1U/16V_4  [C0402]  186.08 71.05 180 top
C4110  10U/6.3V_4  [C0402_2]  170.66 81.71 180 bottom
C4111  0.1U/16V_4  [C0402]  170.66 80.62 0 bottom
C4112  *4.7p/50V_4  [C0402]  182.45 83.69 180 bottom
C4113  *390P/50V_4  [C0402]  184.55 83.13 90 bottom
C4114  0.1U/25V_4  [C0402]  196.19 74.86 270 top
C4200  0.1U/16V_4  [C0402]  195.1 5.92 180 top
C4203  *0.1U/16V_4  [C0402]  190.95 3.86 270 top
C4204  *39P/50V_4  [C0402]  185.34 7.11 0 top
C4205  0.1U/16V_4  [C0402]  212.77 9.45 0 top
C4206  4.7U/6.3V_4  [C0402_2]  209.64 8.53 270 bottom
C4207  18P/50V_4  [C0402]  207.57 3.45 90 top
C4208  56P/50V_4  [C0402]  202.49 5.71 270 top
C4209  6.8P/50V_4  [C0402]  185.62 4.44 270 top
C4210  0.1U/16V_4  [C0402]  203.45 5.71 90 top
C4211  0.1U/25V_2  [C0201]  187.54 4.32 90 top
C4212  *18P/50V_4  [C0402]  186.58 4.44 90 top
C4213  4.7U/6.3V_4  [C0402_2]  201.42 5.71 270 top
C4214  10U/6.3V_4  [C0402_2]  200.23 5.71 90 top
C4215  1000P/50V_4  [C0402]  203.3 45.51 270 bottom
C4216  0.1U/16V_4  [C0402]  201.27 45.51 270 bottom
C4217  2200P/50V_4  [C0402]  202.28 45.51 270 bottom
C4218  *22P/50V_4  [C0402]  190.19 41.98 270 bottom
C4219  *22P/50V_4  [C0402]  190.19 43.76 90 bottom
C4300  0.1U/16V_4  [C0402]  13.63 2.89 270 top
C4301  1000P/50V_4  [C0402]  12.63 2.9 270 top
C4302  0.1U/16V_4  [C0402]  12.47 7.53 90 top
C4303  2200P/50V_4  [C0402]  13.46 7.89 90 top
C4304  0.22U/10V_4  [C0402]  20.69 8.17 180 bottom
C4306  0.22U/10V_4  [C0402]  20.69 9.14 180 bottom
C4307  0.22U/10V_4  [C0402]  17.12 10.01 270 bottom
C4308  0.22U/10V_4  [C0402]  16.1 10.01 270 bottom
C4309  0.22U/10V_4  [C0402]  16.74 12.24 180 bottom
C4310  0.22U/10V_4  [C0402]  16.74 13.25 180 bottom
C4311  0.22U/10V_4  [C0402]  17.2 15.59 180 bottom
C4312  0.22U/10V_4  [C0402]  17.19 16.6 180 bottom
C4313  3.3P/50V_4  [C0402]  11.48 7.53 90 top
C4314  68P/50V_4  [C0402]  11.35 2.69 270 top
C4315  *6.8P/50V_4  [C0402]  24 5.64 0 top
C4400  10u/6.3V_4  [C0402_2]  149.02 9.04 0 top
C4401  0.1U/16V_4  [C0402]  32.92 10.41 270 bottom
C4402  4.7U/6.3V_4  [C0402_2]  34.01 10.41 270 bottom
C4403  220p/50V_4  [C0402]  191.95 32.69 0 top
C4404  0.1U/16V_4  [C0402]  191.95 33.65 180 top
C4405  *10P/50V_4  [C0402]  40.79 8.61 270 top
C4406  10P/50V_4  [C0402]  41.78 7.52 90 top
C4700  10U/6.3V_4  [C0402_2]  196.47 11.38 90 top
C4701  *10U/6.3V_4  [C0402_2]  200 15.95 180 bottom
C4702  0.1U/16V_4  [C0402]  198.65 15.31 90 bottom
C4703  0.1U/16V_4  [C0402]  195.4 11.38 90 top
C4704  *10U/6.3V_4  [C0402_2]  194.66 26.21 0 top
C4705  0.1U/16V_4  [C0402]  194.96 24.79 180 top
C4706  220p/50V_4  [C0402]  174.34 5.66 0 top
C4707  1uF/6.3V_4  [C0402]  188.57 16.99 180 top
C4708  2200P/25V_2  [C0201]  194.59 9.88 270 top
C4709  2200P/25V_2  [C0201]  193.7 14.73 90 bottom
C4710  2200P/25V_2  [C0201]  196.76 13.64 90 bottom
C4711  2200P/25V_2  [C0201]  193.67 9.68 180 top
C4712  1u/6.3V_2  [C0201]  191.64 15.62 270 bottom
C4713  1u/6.3V_2  [C0201]  195.48 15.57 0 bottom
C4714  0.1U/16V_4  [C0402]  175.74 59.92 270 top
C4715  4.7U/6.3V_4  [C0402_2]  188.52 13.21 0 top
C4716  0.1U/16V_4  [C0402]  201.88 19.76 270 top
C4717  0.1U/16V_4  [C0402]  188.57 17.96 180 top
C4718  0.1U/16V_4  [C0402]  187.15 18.46 270 top
C4719  0.1U/16V_4  [C0402]  190.31 19.96 270 bottom
C4720  10U/6.3V_4  [C0402_2]  194.87 12.22 270 bottom
C4721  0.1U/16V_4  [C0402]  193.8 12.22 90 bottom
C4722  *10P/50V_4  [C0402]  202.31 12.55 180 top
C4800  *EGA10402V05AH_0.2p  [R0402]  163.4 100.4 180 top
C4801  0.1u/6.3V_2  [C0201]  201.57 16.1 180 top
C4802  *390P/50V_4  [C0402]  202.22 18.01 90 top
C4804  *0.1U/16V_4  [C0402]  197.69 15.31 90 bottom
C4805  *EGA10402V05AH_0.2p  [R0402]  162.86 102.44 180 top
C4806  0.1U/16V_4  [C0402]  188.75 27.12 90 top
C4807  *0.1U/16V_4  [C0402]  202.31 15.24 180 top
C4808  1U/6.3V_4  [C0402]  169.14 36.01 0 top
C5000  *0.1U/16V_4  [C0402]  177.09 62.53 0 top
C5001  0.1U/16V_4  [C0402]  134.01 11.91 180 bottom
C5029  *EGA10402V05AH_0.2p  [R0402]  125.14 9.37 180 top
C5031  0.1u/6.3V_2  [C0201]  16.63 39.27 90 top
C5034  *EGA10402V05AH_0.2p  [R0402]  126.49 9.78 270 top
C5045  *1uF/6.3V_4  [C0402]  47.76 11.32 90 bottom
C5100  *4.7U/6.3VS_4  [C0402]  167.59 58.23 270 top
C5107  *4.7U/6.3VS_4  [C0402]  160.97 58.58 0 top
C5108  *10P/50V_4  [C0402]  165.05 67.64 90 top
C5109  0.1U/16V_2  [C0201]  162.53 58.49 90 top
C5110  0.1U/16V_2  [C0201]  166.58 58.61 90 top
C5111  0.1U/16V_2  [C0201]  163.58 66.27 270 top
C5112  *0.1U/16V_2  [C0201]  168.6 63.83 180 top
C5201  4.7U/6.3V_4  [C0402_2]  152.6 10.49 90 top
C5202  SYT43L05SMD  [ESD3-0_985X0_585]  156.99 10.01 270 bottom
C5203  SYT43L05SMD  [ESD3-0_985X0_585]  158.97 10.57 180 bottom
C5204  *10P/50V_4  [C0402]  36 5.51 0 top
C5205  *10P/50V_4  [C0402]  37.72 5.51 180 top
C5206  *12P/50V_4  [C0402]  41.16 5.51 180 top
C5207  0.1U/16V_4  [C0402]  42.58 9.11 180 bottom
C5208  *12P/50V_4  [C0402]  39.44 5.51 0 top
C5209  *47U/6.3V_6  [C0603]  39.79 8.42 0 bottom
C5210  *47U/6.3V_6  [C0603]  42.71 7.91 180 bottom
C5400  4.7U/6.3V_4  [C0402_2]  30.99 66.88 270 bottom
C5401  0.1U/16V_4  [C0402]  31.49 62.18 270 bottom
C5402  *220P/50V_4  [C0402]  30.12 57.83 90 bottom
C5403  *220P/50V_4  [C0402]  35.71 59.18 180 bottom
C5404  VARISTOR  [C0402]  32.11 59.73 180 bottom
C5405  *10P/50V_4  [C0402]  32.11 60.74 0 bottom
C5406  0.01U/50V_4  [C0402]  93.29 81.23 180 bottom
C5410  0.1U/16V/X7R_4  [C0402]  31.98 78.38 270 bottom
C5411  2200P/50V_4  [C0402]  70.53 46.12 270 top
C5412  0.1U/16V/X7R_4  [C0402]  184.2 11.48 180 top
C5413  2200P/50V_4  [C0402]  154.25 16.74 270 bottom
C5600  0.1U/16V_4  [C0402]  158.24 94.99 270 top
C5601  82P/50V_4  [C0402]  159.23 94.99 90 top
C5604  0.1u/16V_4  [C0402]  201.22 30.43 270 bottom
C5605  *0.1u/16V_4  [C0402]  200.12 30.73 270 bottom
C5606  0.1U/16V_4  [C0402]  164.08 74.98 0 top
C5900  0.22u/25V_2  [C0201]  177.02 98.62 180 top
C5901  0.22u/25V_2  [C0201]  177.02 99.76 180 top
C5904  0.22u/25V_2  [C0201]  176.63 96.21 180 top
C5905  0.22u/25V_2  [C0201]  176.63 97.35 180 top
C5908  0.22u/25V_2  [C0201]  177.02 91.63 180 top
C5909  0.22u/25V_2  [C0201]  177.02 92.78 180 top
C5912  0.22u/25V_2  [C0201]  177.02 94.05 180 top
C5913  0.22u/25V_2  [C0201]  177.02 95.19 180 top
C5916  10p/50V_4  [C0402]  189.84 101.57 270 bottom
C5917  10p/50V_4  [C0402]  187.99 102.29 180 bottom
C5918  2.2U/6.3V_4  [C0402]  181.07 98.05 270 bottom
C5919  2.2U/6.3V_4  [C0402]  184.54 98.29 0 top
C5920  47U/6.3V_6  [C0603]  177.14 103.58 0 top
C5921  2.2U/6.3V_4  [C0402]  185.44 93.34 90 top
C5922  2.2U/6.3V_4  [C0402]  183.87 93.75 0 top
C5923  2.2U/6.3V_4  [C0402]  186.96 98.64 270 top
C5924  10U/10V_4  [C0402_2]  188.05 98.67 270 top
C5925  18p/25V_2  [C0201]  185.96 98.26 180 top
C5926  4.7U/6.3V_4  [C0402_2]  187.28 96.97 0 top
C5927  4.7U/6.3V_4  [C0402_2]  187.28 95.79 0 top
C5928  *180P/25V_4  [C0402]  182.71 94.77 180 top
C5929  2.2U/6.3V_4  [C0402]  183.09 95.75 180 top
C5930  2.2U/6.3V_4  [C0402]  185.56 97.09 0 top
C5931  2.2U/6.3V_4  [C0402]  185.45 95.82 0 top
C5932  2.2U/6.3V_4  [C0402]  182.79 98.29 180 top
C5933  10U/10V_4  [C0402_2]  183.17 100.71 90 bottom
C5934  2.2U/6.3V_4  [C0402]  184.3 100.72 90 bottom
C5935  18p/25V_2  [C0201]  178.76 102.61 270 bottom
C5936  47U/6.3V_6  [C0603]  182.95 96.97 0 top
C5937  0.1U/10V_2  [C0201]  177.16 63.9 180 bottom
C5938  47U/6.3V_6  [C0603]  171.95 103.06 90 top
C5939  2.2U/6.3V_4  [C0402]  174.65 102.18 180 top
C5940  *10P/50V_4  [C0402]  188.14 89.89 0 top
C5941  *10P/50V_4  [C0402]  188.14 88.92 0 top
C6100  0.1U/16V_4  [C0402]  191.79 88.21 270 top
C6101  0.1U/16V_4  [C0402]  192.76 88.21 270 top
C6102  1uF/6.3V_4  [C0402]  190.83 88.21 90 top
C6103  0.1U/16V_4  [C0402]  194.77 80.72 0 bottom
C6104  1uF/6.3V_4  [C0402]  189.56 89.81 0 bottom
C6105  0.1U/16V_4  [C0402]  192.68 90.18 270 bottom
C6106  0.1U/16V_4  [C0402]  189.81 82.37 90 top
C6107  390P/50V_4  [C0402]  188.03 86.76 0 top
C6108  390P/50V_4  [C0402]  188.03 85.75 0 top
C6109  0.1U/16V_2  [C0201]  198.85 94.49 0 bottom
C6110  0.1U/16V_2  [C0201]  197.38 96.42 90 bottom
C6111  0.1U/16V_2  [C0201]  196.26 96.42 90 bottom
C6112  22U/6.3V_6  [C0603]  198.3 92.83 0 top
C6113  22U/6.3V_6  [C0603]  193.95 88.14 270 top
C6200  0.1U/16V_4  [C0402]  200.07 89.2 270 top
C6201  470P/50V_4  [C0402]  201.13 89.2 270 top
C6202  0.1U/16V_4  [C0402]  200.66 67.49 0 top
C6203  470P/50V_4  [C0402]  200.66 66.47 0 top
C6204  1000P/50V_4  [C0402]  202.22 89.19 90 top
C6205  1000P/50V_4  [C0402]  201.45 64.49 180 top
C6206  0.1U/16V_4  [C0402]  198.81 91.62 180 top
C6207  0.1U/16V_4  [C0402]  198.81 90.61 180 top
C6208  0.1U/16V_4  [C0402]  198.63 69.28 180 top
C6209  0.1U/16V_4  [C0402]  198.63 68.27 180 top
C6210  SYT43L05SMD  [ESD3-0_985X0_585]  200.16 91.25 90 bottom
C6211  SYT43L05SMD  [ESD3-0_985X0_585]  199.57 70.53 90 bottom
C6212  100u/6.3V_12  [C1206]  203.93 62.88 180 bottom
C6213  1U/6.3V_4  [C0402]  208.1 81.86 180 top
C6214  2.2u/10V_4  [C0402]  196.59 79.88 180 top
C6215  0.1U/16V_2  [C0201]  195.83 81.51 0 top
C6216  470p/50V_4  [C0402]  200.41 83.19 180 bottom
C6217  100u/6.3V_12  [C1206]  203.66 81.68 180 bottom
C6306  *10u/25V_6  [C0603]  211.17 106.98 90 bottom
C6308  0.33u/25V_2  [C0201]  207.62 109.8 180 top
C6309  0.33u/25V_2  [C0201]  207.62 109.04 180 top
C6310  0.22u/25V_2  [C0201]  208 112.47 180 top
C6311  0.22u/25V_2  [C0201]  208 111.71 180 top
C6312  0.33u/25V_2  [C0201]  207.62 102.44 180 top
C6313  0.33u/25V_2  [C0201]  207.62 103.2 180 top
C6314  0.22u/25V_2  [C0201]  207.24 105.48 180 top
C6315  0.22u/25V_2  [C0201]  207.24 106.25 180 top
C6600  22U/6.3VS_4  [C0402_2]  53.44 68.6 180 bottom
C6601  10u/6.3V_4  [C0402_2]  62.81 57.6 270 top
C6602  10u/6.3V_4  [C0402_2]  53.44 66.06 180 bottom
C6603  *0.1u/16V_4  [C0402]  78.1 58.19 270 bottom
C6604  1u/6.3V_4  [C0402]  65.3 57.6 90 top
C6605  1u/6.3V_4  [C0402]  68.73 74.65 270 top
C6606  1u/6.3V_4  [C0402]  61.67 57.6 90 top
C6607  1u/6.3V_4  [C0402]  68.46 76.83 270 top
C6608  22U/6.3VS_4  [C0402_2]  69.82 74.65 90 top
C6609  0.22u/25V_2  [C0201]  75.05 63.29 90 bottom
C6610  0.22u/25V_2  [C0201]  74.34 63.29 90 bottom
C6612  4.7u/6.3V_4  [C0402_2]  64.08 57.6 90 top
C6613  1u/6.3V_4  [C0402]  73.07 74.65 270 top
C6614  1u/6.3V_4  [C0402]  72.1 74.72 270 top
C6615  1u/6.3V_4  [C0402]  53.44 67.33 0 bottom
C6616  22U/6.3VS_4  [C0402_2]  73.7 80.71 90 top
C6617  22U/6.3VS_4  [C0402_2]  71.01 74.77 90 top
C6619  0.1u/16V_4  [C0402]  70.71 84.5 90 top
C6620  22U/6.3VS_4  [C0402_2]  64.44 70 270 top
C6621  1u/6.3V_4  [C0402]  69.82 82.5 90 top
C6622  22u/6.3V_6  [C0603]  70.98 78.97 180 top
C6623  4.7u/6.3V_4  [C0402_2]  63.88 91.77 270 bottom
C6624  10u/6.3V_4  [C0402_2]  58.37 62.81 270 bottom
C6625  0.22u/25V_2  [C0201]  73.63 63.29 90 bottom
C6626  22U/6.3VS_4  [C0402_2]  66.86 72.62 270 top
C6628  1u/6.3V_4  [C0402]  71.27 82.47 90 top
C6630  4.7u/6.3V_4  [C0402_2]  72.36 82.47 90 top
C6631  22u/6.3V_6  [C0603]  66.31 78.49 90 top
C6632  22U/6.3VS_4  [C0402_2]  69.62 72.84 90 top
C6633  10u/6.3V_4  [C0402_2]  59.56 62.81 270 bottom
C6634  0.22u/25V_2  [C0201]  72.92 63.29 90 bottom
C6635  22u/6.3V_6  [C0603]  62.56 92.43 270 bottom
C6636  4.7u/6.3V_4  [C0402_2]  69.67 71.02 0 top
C6637  22u/6.3V_6  [C0603]  64.41 71.93 180 top
C6638  10u/6.3V_4  [C0402_2]  69.54 76.83 90 top
C6639  10u/6.3V_4  [C0402_2]  70.03 80.77 270 top
C6640  0.22u/25V_2  [C0201]  72.79 62.13 90 bottom
C6641  10u/6.3V_4  [C0402_2]  66.52 81.33 90 top
C6642  4.7u/6.3V_4  [C0402_2]  73.58 82.47 90 top
C6643  0.22u/25V_2  [C0201]  72.08 62.13 90 bottom
C6644  10u/6.3V_4  [C0402_2]  68.83 80.77 270 top
C6645  1u/6.3V_4  [C0402]  75.09 82.57 0 top
C6646  1u/6.3V_4  [C0402]  65.56 70 90 top
C6647  22U/6.3VS_4  [C0402_2]  68.07 72.65 270 top
C6648  1u/6.3V_4  [C0402]  62 71.07 0 top
C6649  22U/6.3VS_4  [C0402_2]  74.26 76.71 270 top
C6650  0.1u/16V_4  [C0402]  75.44 83.92 270 top
C6651  1u/6.3V_4  [C0402]  71.09 71.19 90 top
C6653  0.1u/16V_4  [C0402]  73.91 84.43 270 top
C6654  1u/6.3V_4  [C0402]  62 70.1 0 top
C6656  0.22u/25V_2  [C0201]  71.37 62.13 90 bottom
C6657  0.22u/25V_2  [C0201]  70.66 62.13 90 bottom
C6662  1u/6.3V_4  [C0402]  67.5 76.83 270 top
C6663  10u/6.3V_4  [C0402_2]  73.08 76.78 270 top
C6664  10u/6.3V_4  [C0402_2]  67.64 74.65 90 top
C6665  47U/6.3VS_6  [C0603]  63.47 78.56 270 top
C6666  10u/6.3V_4  [C0402_2]  71.24 80.74 90 top
C6667  47U/6.3VS_6  [C0603]  65.45 75.03 0 top
C6668  10u/6.3V_4  [C0402_2]  72.44 80.74 90 top
C6669  47U/6.3VS_6  [C0603]  68.36 79.02 0 top
C6670  10u/6.3V_4  [C0402_2]  70.99 72.92 90 top
C6671  47U/6.3VS_6  [C0603]  64.89 78.48 90 top
C6672  10u/6.3V_4  [C0402_2]  70.72 76.76 270 top
C6673  1u/6.3V_4  [C0402]  85.93 79.7 180 top
C6674  47U/6.3VS_6  [C0603]  65.45 76.45 180 top
C6675  10u/6.3V_4  [C0402_2]  71.9 76.83 270 top
C6676  1u/6.3V_4  [C0402]  85.93 80.97 180 top
C6677  10u/6.3V_4  [C0402_2]  75.13 75.24 0 top
C6678  4.7u/6.3V_4  [C0402_2]  82.88 77.04 90 top
C6680  0.1u/16V_4  [C0402]  77.05 61.39 180 bottom
C6682  2.2U/10V_4  [C0402]  83.11 63.45 270 top
C6683  0.1u/16V_4  [C0402]  85.67 69.67 270 top
C6684  2.2U/10V_4  [C0402]  74.62 70.1 90 top
C6686  22u/6.3V_6  [C0603]  74.98 73.33 270 top
C6687  1u/6.3V_4  [C0402]  57.73 61.41 180 bottom
C6688  1u/6.3V_4  [C0402]  61.11 60.45 270 top
C6689  1u/6.3V_4  [C0402]  62.13 60.45 270 top
C6693  22U/6.3VS_4  [C0402_2]  53.44 69.8 180 bottom
C6697  0.47U/25V_4  [C0402]  67.51 70 90 top
C6698  1u/6.3V_4  [C0402]  71.12 94.46 180 top
C6699  4.7u/6.3V_4  [C0402_2]  72.9 94 180 top
C6700  1u/6.3V_4  [C0402]  64.49 81.81 270 top
C6701  1u/6.3V_4  [C0402]  62.63 75.77 0 top
C6702  1u/6.3V_4  [C0402]  62.51 80.49 0 top
C6703  1u/6.3V_4  [C0402]  62.9 74.8 0 top
C6704  1u/6.3V_4  [C0402]  62.9 73.81 0 top
C6705  1u/6.3V_4  [C0402]  67.6 82.5 270 top
C6706  1u/6.3V_4  [C0402]  68.86 82.5 270 top
C6707  10u/6.3V_4  [C0402_2]  62.23 82.57 270 top
C6708  22U/6.3VS_4  [C0402_2]  62.17 78.84 270 top
C6709  1u/6.3V_4  [C0402]  65.45 81.81 270 top
C6710  22U/6.3VS_4  [C0402_2]  38.1 61.41 90 top
C6711  22U/6.3VS_4  [C0402_2]  62.18 72.42 270 top
C6712  10u/6.3V_4  [C0402_2]  63.41 82.57 270 top
C6713  10u/6.3V_4  [C0402_2]  60.53 73.56 180 top
C6714  0.1u/16V_4  [C0402]  91.16 96.4 0 bottom
C6715  22U/6.3VS_4  [C0402_2]  64.39 62.81 90 bottom
C6716  1u/6.3V_4  [C0402]  65.48 62.81 270 bottom
C6717  1u/6.3V_4  [C0402]  62.23 77.11 270 top
C6718  4.7u/6.3V_4  [C0402_2]  66.57 62.81 90 bottom
C6719  3.9P/50V_4  [C0402]  53.41 91.89 0 top
C6800  1u/6.3V_4  [C0402]  74.88 80.71 90 top
C6802  1u/6.3V_4  [C0402]  75.16 78.61 0 top
C6803  0.1u/16V_4  [C0402]  73.46 78.89 270 top
C6806  10p/50V_4  [C0402]  71.97 91.29 180 bottom
C6807  10p/50V_4  [C0402]  73.74 91.29 0 bottom
C6808  *1000P/50V_4  [C0402]  48.97 56.59 180 bottom
C6809  1000p/50V_4  [C0402]  61.36 92.17 90 bottom
C6810  *1000P/50V_4  [C0402]  37.41 58.14 270 bottom
C6818  0.1U/16V_4  [C0402]  64.23 97.71 90 top
C6900  0.1u/16V_4  [C0402]  91.16 97.55 0 bottom
C6901  0.033u/16V_4  [C0402]  84.3 85.19 90 bottom
C6902  1u/6.3V_4  [C0402]  69.29 92.28 180 top
C7000  1U/6.3V_4  [C0402]  34.41 89.84 0 top
C7001  1U/6.3V_4  [C0402]  32.43 69.7 180 bottom
C7002  1U/6.3V_4  [C0402]  45.29 84.88 180 top
C7003  1U/6.3V_4  [C0402]  34.53 86.36 180 top
C7004  1U/6.3V_4  [C0402]  46.86 90.88 90 top
C7005  1U/6.3V_4  [C0402]  34.11 75.51 270 top
C7006  1U/6.3V_4  [C0402]  46.71 86.03 270 top
C7007  1U/6.3V_4  [C0402]  41.73 79.17 0 bottom
C7008  1U/6.3V_4  [C0402]  46.63 83.64 270 top
C7009  1U/6.3V_4  [C0402]  33.86 99.26 90 bottom
C7010  1U/6.3V_4  [C0402]  42.77 60.48 270 bottom
C7011  1U/6.3V_4  [C0402]  32.89 99.26 90 bottom
C7012  1U/6.3V_4  [C0402]  40.89 79.07 180 top
C7013  1U/6.3V_4  [C0402]  32.81 68.81 0 top
C7014  1U/6.3V_4  [C0402]  34.03 64.41 270 top
C7015  1U/6.3V_4  [C0402]  44.24 93.32 90 top
C7016  1U/6.3V_4  [C0402]  41.73 65.1 270 top
C7017  1U/6.3V_4  [C0402]  41.76 60.48 270 bottom
C7018  1U/6.3V_4  [C0402]  46.3 92.23 0 top
C7019  1U/6.3V_4  [C0402]  41.68 82.65 0 top
C7020  1U/6.3V_4  [C0402]  34.4 72.14 270 top
C7021  1U/6.3V_4  [C0402]  31.39 95.93 180 bottom
C7022  10U/6.3V_4  [C0402_2]  46.61 68.96 270 top
C7023  10U/6.3V_4  [C0402_2]  39.98 79.17 180 bottom
C7024  10U/6.3V_4  [C0402_2]  38.15 79.78 90 top
C7025  10U/6.3V_4  [C0402_2]  37.36 76.43 180 top
C7026  10U/6.3V_4  [C0402_2]  45.29 90.4 180 top
C7027  10U/6.3V_4  [C0402_2]  38.89 76.68 270 top
C7028  10U/6.3V_4  [C0402_2]  33.89 93.14 270 top
C7029  1U/6.3V_4  [C0402]  38.15 81.86 0 top
C7030  1U/6.3V_4  [C0402]  41.7 80.64 0 top
C7031  1U/6.3V_4  [C0402]  39.9 82.62 180 top
C7032  1U/6.3V_4  [C0402]  32.81 69.8 0 top
C7033  1U/6.3V_4  [C0402]  43.48 79.17 0 bottom
C7034  1U/6.3V_4  [C0402]  43.76 84.27 270 top
C7035  1U/6.3V_4  [C0402]  31.39 94.97 180 bottom
C7036  1U/6.3V_4  [C0402]  44.4 87.5 90 top
C7037  1U/6.3V_4  [C0402]  32.31 86.08 180 top
C7038  1U/6.3V_4  [C0402]  37.31 94.74 270 top
C7039  1U/6.3V_4  [C0402]  45.59 93.6 180 top
C7040  1U/6.3V_4  [C0402]  41.25 91.79 270 top
C7041  1U/6.3V_4  [C0402]  41.98 67.99 90 top
C7042  1U/6.3V_4  [C0402]  43.81 60.48 270 bottom
C7043  10U/6.3V_4  [C0402_2]  45.36 67.03 0 top
C7044  10U/6.3V_4  [C0402_2]  34.82 95.55 270 top
C7045  10U/6.3V_4  [C0402_2]  34.9 83.67 90 top
C7046  10U/6.3V_4  [C0402_2]  38.61 74.55 270 top
C7047  10U/6.3V_4  [C0402_2]  33.04 97.79 0 bottom
C7048  22U/6.3V_6  [C0603]  51.94 95.22 270 bottom
C7049  22U/6.3V_6  [C0603]  32 68.48 0 bottom
C7050  22U/6.3V_6  [C0603]  29.18 77.56 0 top
C7051  22U/6.3V_6  [C0603]  53.36 95.22 270 bottom
C7052  22U/6.3V_6  [C0603]  29.18 76.02 0 top
C7053  22U/6.3V_6  [C0603]  45.01 60.45 90 bottom
C7054  22U/6.3V_6  [C0603]  29.18 74.48 0 top
C7055  22U/6.3V_6  [C0603]  37.16 79.45 0 bottom
C7056  22U/6.3V_6  [C0603]  29.26 70.69 0 top
C7057  22U/6.3V_6  [C0603]  29.26 69.03 0 top
C7058  820p/50V_4  [C0402]  31.14 94.94 0 top
C7059  0.01U/50V_4  [C0402]  34.39 70.41 90 top
C7060  0.01U/50V_4  [C0402]  34.77 88.49 270 top
C7061  820p/50V_4  [C0402]  32.41 73.4 0 bottom
C7200  *68P/50V_2  [C0201]  114.42 17.96 90 top
C7201  *2200P/50V_2  [C0201]  120.62 18.51 90 top
C7202  0.1U/25V_2  [C0201]  119.66 18.51 90 top
C7203  68P/50V_4  [C0402]  78.71 19.02 270 top
C7204  2200P/50V_4  [C0402]  79.75 19.02 270 top
C7205  68P/50V_4  [C0402]  35.66 18.95 180 top
C7206  68P/50V_4  [C0402]  60.12 18.21 270 top
C7207  2200P/50V_4  [C0402]  59.15 18.21 270 top
C7208  2200P/50V_4  [C0402]  201.3 7.71 270 top
C7209  0.1U/16V_4  [C0402]  202.32 7.75 270 top
C7210  0.1U/16V_4  [C0402]  21.63 61.78 270 top
C7215  2200P/50V_4  [C0402]  59.89 56.08 180 top
C7216  0.1U/16V_4  [C0402]  60.27 57.1 0 top
C7217  0.1U/25V_4  [C0402]  154.18 94.66 90 bottom
C7218  0.1U/25V_4  [C0402]  170.53 84.43 90 bottom
C7219  2.2U/10V_4  [C0402]  203.02 9.5 90 top
C7220  *0.1U/25V_4  [C0402]  11.83 27.58 270 top
C7221  *2.2u/25V_4  [C0402_2]  11.99 32.89 180 top
C7222  *2.2u/25V_4  [C0402_2]  13.23 27.86 180 top
C7223  3.3P/50V_4  [C0402]  108.35 55.42 270 top
C7224  3.3P/50V_4  [C0402]  134.82 56.64 180 top
C7225  3.3P/50V_4  [C0402]  56.13 24.81 90 top
C7226  3.3P/50V_4  [C0402]  153.03 26.13 270 top
C7227  68P/50V_4  [C0402]  169.54 20.34 90 top
C7228  2200P/50V_4  [C0402]  134.95 17.27 270 bottom
C7229  2200P/50V_4  [C0402]  61.16 18.21 270 top
C7230  2200P/50V_4  [C0402]  66.04 106.53 180 top
C7231  68P/50V_4  [C0402]  65.02 15.49 90 bottom
C7232  2200P/50V_4  [C0402]  59.46 17.93 0 bottom
C7233  2200P/50V_4  [C0402]  28.32 48.71 90 top
C7234  2200P/50V_4  [C0402]  10.28 2.69 270 top
C7236  2200P/50V_4  [C0402]  23.95 30.4 180 top
C7237  0.1U/16V_2  [C0201]  20.04 8.74 270 top
C7238  2.2p/50V_4  [C0402]  89.63 99.46 180 top
C7239  0.1U/16V_2  [C0201]  16.86 7.57 0 top
C7600  4.7U/6.3V_4  [C0402_2]  182.31 38.22 270 top
C7601  0.1U/16V_4  [C0402]  181.17 38.22 90 top
C7602  *5.6P/50V_4  [C0402]  181.89 35.56 0 top
C7603  *5.6P/50V_4  [C0402]  179.42 34.74 180 top
C7604  0.1U/16V_4  [C0402]  176.1 44.66 270 top
C7605  0.1U/16V_4  [C0402]  175.11 44.66 270 top
C7606  *5.6P/50V_4  [C0402]  176.43 33.35 0 top
C7607  1U/6.3V_4  [C0402]  176.71 35.13 90 top
C7608  *5.6P/50V_4  [C0402]  175.05 32.97 90 top
C7609  *5.6P/50V_4  [C0402]  173.81 33.5 270 top
C7610  0.1U/16V_4  [C0402]  172.27 42.74 270 top
C7611  10U/6.3V_4  [C0402_2]  171.77 40.06 180 top
C7612  0.1U/16V_4  [C0402]  171.78 41.15 0 top
C7613  4.7U/6.3V_4  [C0402_2]  169.37 40.64 0 top
C7614  0.1U/16V_4  [C0402]  171.42 36.4 90 top
C7615  4.7U/6.3V_4  [C0402_2]  172.01 38.86 180 top
C7616  0.1U/16V_4  [C0402]  172.08 37.77 0 top
C7617  0.1U/16V_4  [C0402]  12.9 26.39 270 top
C7618  470p/50V_4  [C0402]  13.92 26.39 90 top
C7619  100u/6.3V_12_H1.6  [C1206]  18.13 21.41 0 bottom
C7700  0.1U/16V_2  [C0201]  122.31 89.37 180 bottom
C7701  0.1u/16V_4  [C0402]  38.87 52.12 180 top
C7730  4.7u/6.3V_4  [C0402_2]  66.52 83.36 270 top
C7731  0.1U/16V_4  [C0402]  92.12 68.96 0 top
C7732  2.2u/25V_4  [C0402_2]  80.9 19.02 90 top
C7733  0.1U/25V_4  [C0402]  81.99 19.02 270 top
C7734  2.2u/25V_4  [C0402_2]  137.84 18.39 90 top
